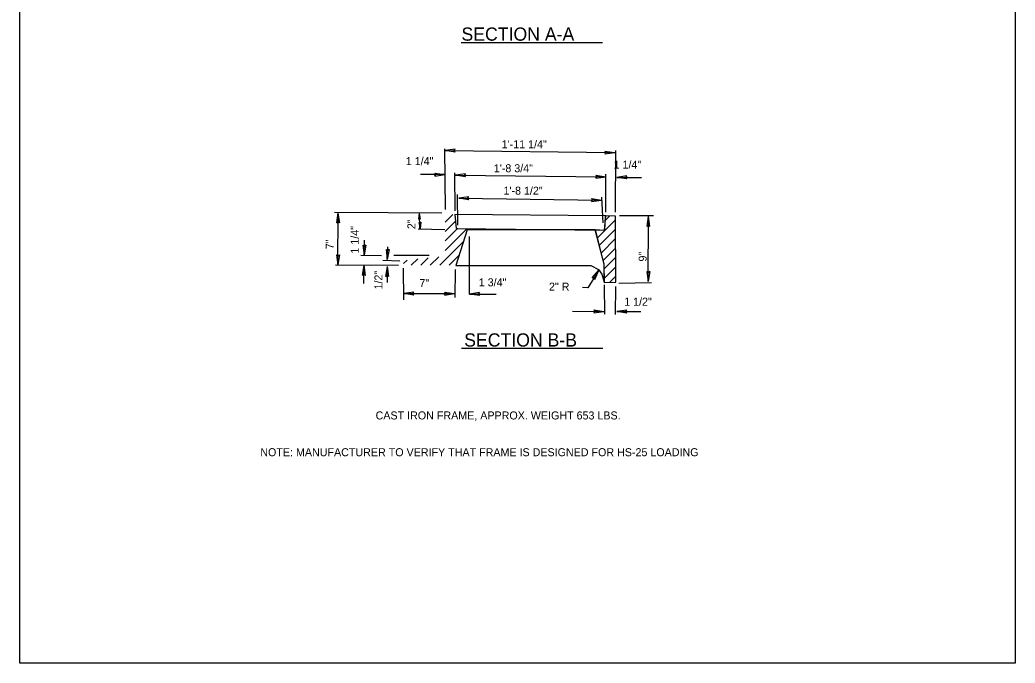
# Model space of a CAD drawing. Extents: x 0.7 to 8.1, y 0.4 to 10.6.
# Drawn here: x 0.66 to 8.12, y 0.37 to 5.19 of the extents above; entities that cross this region are included whole.
import ezdxf

# ---------------------------------------------------------------- set-up
doc = ezdxf.new("R2010")
doc.units = 0
for name, color, linetype in [('DETL-DIMS', 7, 'Continuous'), ('DETL-LINE', 7, 'Continuous'), ('DETL-NOTE', 7, 'Continuous'), ('DETL-TITL', 7, 'Continuous'), ('TTLB-TEXT', 7, 'Continuous')]:
    doc.layers.add(name, color=color, linetype=linetype)

msp = doc.modelspace()

# ---------------------------------------------------------------- linework, layer by layer
at = {"layer": 'DETL-DIMS'}
for p, q in [((3.8543, 3.774), (3.849, 4.2281)), ((3.8516, 4.2147), (5.1247, 4.1986)), ((3.9268, 4.2247), (3.8517, 4.2147)), ((3.9265, 4.2028), (3.8517, 4.2147)), ((3.9268, 4.2247), (3.9173, 4.2139)), ((3.9265, 4.2028), (3.9173, 4.2139)), ((5.0496, 4.1886), (5.0591, 4.1994)), ((5.0496, 4.1886), (5.0591, 4.1994)), ((5.0496, 4.1886), (5.1247, 4.1986)), ((5.0496, 4.1886), (5.1247, 4.1986)), ((5.0499, 4.2105), (5.1247, 4.1986)), ((5.0499, 4.2105), (5.0591, 4.1994)), ((5.0499, 4.2105), (5.1247, 4.1986)), ((5.0499, 4.2105), (5.0591, 4.1994)), ((5.1301, 3.7525), (5.1328, 4.2147)), ((3.849, 4.0347), (3.6663, 4.0347)), ((3.7739, 4.0237), (3.849, 4.0347)), ((3.7739, 4.0237), (3.7833, 4.0347)), ((3.774, 4.0456), (3.849, 4.0347)), ((3.774, 4.0456), (3.7833, 4.0347)), ((3.9268, 3.7633), (3.9242, 4.0481)), ((4.0047, 4.0395), (3.9295, 4.0293)), ((3.9295, 4.0293), (5.0576, 4.0185)), ((4.0044, 4.0177), (3.9295, 4.0293)), ((4.0047, 4.0395), (3.9952, 4.0287)), ((4.9827, 4.0302), (5.0576, 4.0186)), ((4.9827, 4.0302), (4.992, 4.0192)), ((5.0576, 3.7525), (5.0576, 4.0374)), ((4.0044, 4.0177), (3.9952, 4.0287)), ((4.9825, 4.0083), (4.992, 4.0192)), ((4.9825, 4.0083), (5.0576, 4.0186)), ((5.1381, 4.0132), (5.3235, 4.0132)), ((5.2132, 4.0241), (5.1382, 4.0132)), ((5.2132, 4.0023), (5.1382, 4.0132)), ((5.2132, 4.0241), (5.2038, 4.0132)), ((5.2132, 4.0023), (5.2038, 4.0132)), ((3.9483, 3.6558), (3.9456, 3.8842)), ((4.0289, 3.8673), (3.9537, 3.8573)), ((3.9537, 3.8573), (5.0253, 3.8439)), ((4.0286, 3.8454), (3.9537, 3.8573)), ((4.0289, 3.8673), (4.0193, 3.8565)), ((4.0286, 3.8454), (4.0193, 3.8565)), ((4.9502, 3.8339), (4.9597, 3.8447)), ((4.9502, 3.8339), (5.0253, 3.8439)), ((4.9505, 3.8558), (5.0253, 3.8439)), ((4.9505, 3.8558), (4.9597, 3.8447)), ((5.0361, 3.6719), (5.028, 3.8654)), ((3.8275, 3.7444), (3.0217, 3.7498)), ((3.0398, 3.6722), (3.0513, 3.7472)), ((3.0486, 3.3575), (3.0513, 3.7471)), ((3.0617, 3.6721), (3.0513, 3.7472)), ((3.6555, 3.6993), (3.661, 3.7445)), ((3.6636, 3.6316), (3.6609, 3.7444)), ((3.6686, 3.6996), (3.661, 3.7445)), ((3.0398, 3.6722), (3.0508, 3.6815)), ((3.0617, 3.6721), (3.0508, 3.6815)), ((3.6555, 3.6993), (3.6619, 3.7051)), ((3.656, 3.6764), (3.6637, 3.6316)), ((3.656, 3.6764), (3.6627, 3.671)), ((3.6686, 3.6996), (3.6619, 3.7051)), ((3.6691, 3.6768), (3.6627, 3.671)), ((3.6691, 3.6768), (3.6637, 3.6316)), ((5.1596, 3.7283), (5.4148, 3.7283)), ((5.3658, 3.6453), (5.3772, 3.7203)), ((5.3745, 3.2339), (5.3772, 3.7203)), ((5.3877, 3.6452), (5.3772, 3.7203)), ((3.6502, 3.6289), (3.849, 3.6235)), ((5.3658, 3.6453), (5.3768, 3.6547)), ((5.3877, 3.6452), (5.3768, 3.6547)), ((3.2446, 3.43), (3.2473, 3.5429)), ((4.0343, 3.1398), (4.0343, 3.5707)), ((3.0382, 3.4326), (3.0486, 3.3575)), ((3.0382, 3.4326), (3.0491, 3.4231)), ((3.0601, 3.4324), (3.0486, 3.3575)), ((3.0601, 3.4324), (3.0491, 3.4231)), ((3.2355, 3.5053), (3.2447, 3.4301)), ((3.2355, 3.5053), (3.2462, 3.4957)), ((3.2574, 3.5048), (3.2447, 3.4301)), ((3.2574, 3.5048), (3.2462, 3.4957)), ((3.4099, 3.4733), (3.4166, 3.3978)), ((3.4099, 3.4733), (3.4203, 3.4633)), ((3.4165, 3.3978), (3.4219, 3.4919)), ((3.4318, 3.4721), (3.4166, 3.3978)), ((3.4318, 3.4721), (3.4203, 3.4633)), ((3.3762, 3.4247), (3.2205, 3.4274)), ((3.3843, 3.3924), (3.5132, 3.3871)), ((3.7335, 3.4274), (3.4676, 3.4274)), ((3.5025, 3.3521), (3.0298, 3.3548)), ((3.2323, 3.2801), (3.2447, 3.3548)), ((3.2323, 3.2801), (3.2434, 3.2892)), ((3.242, 3.2178), (3.2446, 3.3548)), ((3.2541, 3.2796), (3.2434, 3.2892)), ((3.2541, 3.2796), (3.2447, 3.3548)), ((3.4083, 3.2717), (3.4192, 3.3468)), ((3.4302, 3.2717), (3.4192, 3.3468)), ((3.4192, 3.2258), (3.4192, 3.3467)), ((3.5428, 3.0968), (3.5401, 3.3333)), ((3.9268, 3.113), (3.9295, 3.3226)), ((5.364, 3.309), (5.3745, 3.2339)), ((5.364, 3.309), (5.3749, 3.2995)), ((5.3858, 3.3088), (5.3745, 3.2339)), ((5.3858, 3.3088), (5.3749, 3.2995)), ((3.4083, 3.2717), (3.4192, 3.2811)), ((3.4302, 3.2717), (3.4192, 3.2811)), ((5.0495, 2.9894), (5.0468, 3.2097)), ((5.1543, 3.2204), (5.3987, 3.2258)), ((3.6178, 3.1535), (3.5428, 3.1425)), ((3.5428, 3.1425), (3.9215, 3.1425)), ((3.6178, 3.1316), (3.5428, 3.1425)), ((3.6178, 3.1535), (3.6084, 3.1425)), ((3.6178, 3.1316), (3.6084, 3.1425)), ((3.8465, 3.1535), (3.9215, 3.1425)), ((3.8465, 3.1535), (3.8558, 3.1425)), ((3.8465, 3.1316), (3.9215, 3.1425)), ((3.8465, 3.1316), (3.8558, 3.1425)), ((4.1093, 3.1508), (4.0343, 3.1398)), ((4.0343, 3.1398), (4.2357, 3.1398)), ((4.1093, 3.1289), (4.0343, 3.1398)), ((4.1093, 3.1508), (4.0999, 3.1398)), ((4.1093, 3.1289), (4.0999, 3.1398)), ((5.1301, 2.9867), (5.1328, 3.1963)), ((4.8078, 3.0108), (5.0415, 3.0082)), ((4.9663, 2.9981), (4.9758, 3.0089)), ((4.9663, 2.9981), (5.0415, 3.0082)), ((4.9666, 3.02), (5.0415, 3.0082)), ((4.9666, 3.02), (4.9758, 3.0089)), ((5.1381, 3.0082), (5.3181, 3.0082)), ((5.2132, 3.0191), (5.1382, 3.0082)), ((5.2132, 2.9973), (5.1382, 3.0082)), ((5.2132, 3.0191), (5.2038, 3.0082)), ((5.2132, 2.9973), (5.2038, 3.0082))]:
    msp.add_line(p, q, dxfattribs=at)
at = {"layer": 'DETL-LINE'}
for p, q in [((3.8517, 3.6787), (3.9086, 3.7356)), ((3.8517, 3.608), (3.9292, 3.6855)), ((4.9929, 3.5593), (5.1292, 3.6955)), ((5.0504, 3.6875), (5.0877, 3.7247)), ((3.8517, 3.5373), (3.9471, 3.6326)), ((3.8517, 3.4666), (4.0139, 3.6288)), ((4.9789, 3.6159), (4.9828, 3.6198)), ((5.007, 3.5026), (5.1295, 3.6251)), ((3.8114, 3.3555), (3.9897, 3.5338)), ((5.0211, 3.446), (5.1298, 3.5547)), ((5.0351, 3.3893), (5.13, 3.4842)), ((3.5406, 3.3676), (3.5673, 3.3943)), ((3.5983, 3.3546), (3.6462, 3.4024)), ((3.6693, 3.3549), (3.725, 3.4106)), ((3.7403, 3.3552), (3.8039, 3.4187)), ((3.8824, 3.3558), (3.955, 3.4284)), ((5.0423, 3.3258), (5.1303, 3.4138)), ((5.0433, 3.2561), (5.1306, 3.3434)), ((5.0848, 3.2268), (5.1309, 3.273))]:
    msp.add_line(p, q, dxfattribs=at)
for points in [[(3.9356, 3.63), (5.0469, 3.6168), (5.0567, 3.7254), (3.9258, 3.7353)], [(4.9778, 3.6201), (5.0418, 3.3625), (5.0438, 3.2254), (5.1311, 3.2284), (5.1291, 3.7231), (5.0529, 3.7261), (5.0458, 3.6154)], [(4.0178, 3.6201), (3.9323, 3.3537), (4.945, 3.3537), (5.0009, 3.3241), (5.0272, 3.2879), (5.0436, 3.2287), (5.0436, 3.3636), (4.9778, 3.6201)]]:
    msp.add_lwpolyline(points, close=True, dxfattribs=at)
at = {"layer": 'DETL-NOTE'}
for p, q in [((4.9547, 3.261), (5.0031, 3.3193)), ((4.9733, 3.2496), (5.0031, 3.3193)), ((4.9547, 3.261), (4.9689, 3.2633)), ((4.9733, 3.2496), (4.9689, 3.2633))]:
    msp.add_line(p, q, dxfattribs=at)
msp.add_lwpolyline([(0.6641, 10.6264), (8.125, 10.6264), (8.125, 0.375), (0.6641, 0.375)], close=True, dxfattribs=at)
msp.add_lwpolyline([(5.0031, 3.3193), (4.9223, 3.1871), (4.8811, 3.1879)], dxfattribs=at)
at = {"layer": 'DETL-TITL'}
for p, q in [((3.9725, 5.0249), (5.0324, 5.0249)), ((3.9752, 2.7337), (5.0351, 2.7337))]:
    msp.add_line(p, q, dxfattribs=at)
at = {"layer": 'TTLB-TEXT'}
msp.add_line((8.1242, 0.375), (8.1242, 0.375), dxfattribs=at)

# ---------------------------------------------------------------- texts
at = {"layer": 'DETL-NOTE'}
for s, p in [('1\'-11 1/4"', (4.276, 4.2314)), (' 1 1/4"', (3.5347, 4.1054)), ('1\'-8 3/4"', (4.2169, 4.0517)), (' 1 1/4"', (5.0925, 4.0786)), ('1\'-8 1/2"', (4.2895, 3.8839)), (' 7"', (3.6368, 3.1918)), ('1 3/4"', (4.1041, 3.1972)), ('2" R', (4.6305, 3.1649)), ('1 1/2"', (5.1945, 3.0521)), ('CAST IRON FRAME, APPROX. WEIGHT 653 LBS.', (3.3308, 2.2001)), ('NOTE: MANUFACTURER TO VERIFY THAT FRAME IS DESIGNED FOR HS-25 LOADING', (2.4664, 1.9245))]:
    msp.add_text(s, height=0.06, dxfattribs=at).set_placement(p)
for s, p in [(' 2"', (3.6292, 3.6034)), ('1 1/4"', (3.2048, 3.4421)), (' 7"', (3.0168, 3.4529)), (' 9"', (5.363, 3.3606)), ('1/2"', (3.3821, 3.1734))]:
    msp.add_text(s, height=0.06, rotation=90, dxfattribs=at).set_placement(p)
at = {"layer": 'DETL-TITL'}
for s, p in [('SECTION A-A', (3.9745, 5.0373)), ('SECTION B-B', (3.9949, 2.746))]:
    msp.add_text(s, height=0.099005, dxfattribs=at).set_placement(p)

doc.saveas('drawing.dxf')
